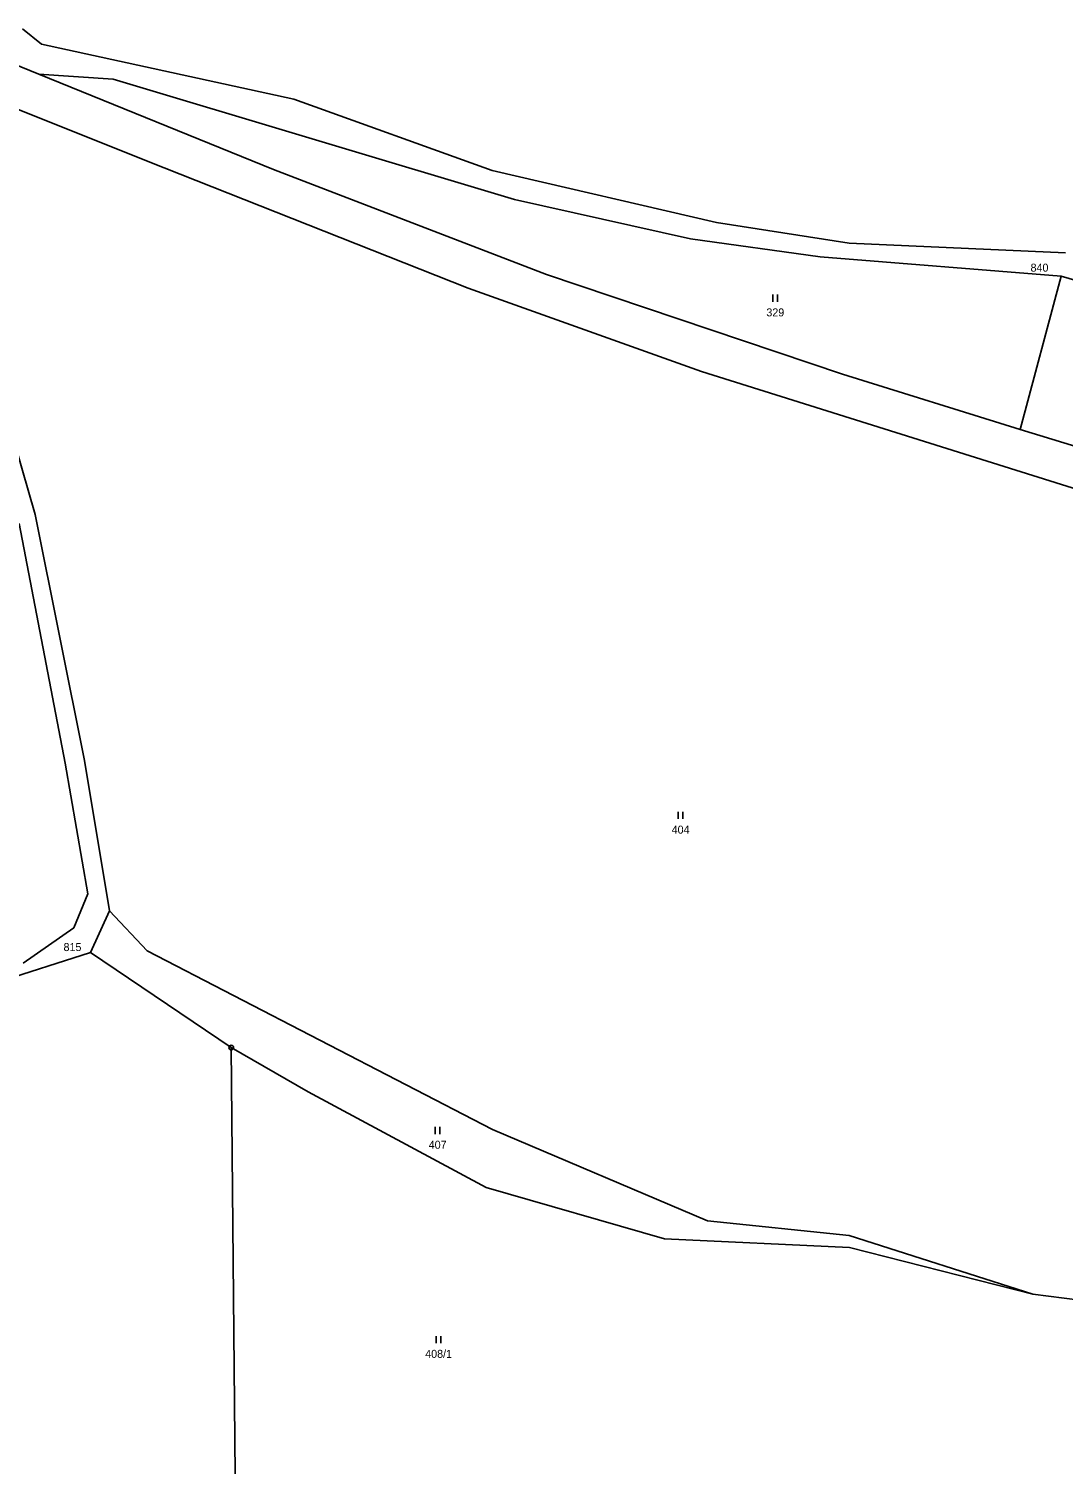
# Model space of a CAD drawing. Extents: x -739410 to -735662, y -942282 to -940043.
# Drawn here: x -736922.9 to -736703.1, y -941395 to -941090 of the extents above; entities that cross this region are included whole.
import ezdxf
from ezdxf.enums import TextEntityAlignment as Align

# ---------------------------------------------------------------- set-up
doc = ezdxf.new("R2010")
doc.units = 0
doc.header["$LTSCALE"] = 0.68
for name, color, linetype, lineweight in [('1', 7, 'Continuous', 25), ('3', 7, 'Continuous', 25), ('8', 7, 'Continuous', 25)]:
    doc.layers.add(name, color=color, linetype=linetype, lineweight=lineweight)
doc.layers.add('2', color=7, linetype='Continuous')

msp = doc.modelspace()

# ---------------------------------------------------------------- linework, layer by layer
at = {"layer": '1'}
for p, q in [((-736920.21, -941093.26), (-736924.25, -941089.98)), ((-736866.59, -941104.95), (-736920.21, -941093.26)), ((-736926.54, -941097.3), (-736920.82, -941099.62)), ((-736904.98, -941100.71), (-736920.82, -941099.62)), ((-736920.82, -941099.62), (-736870.95, -941119.89)), ((-736819.74, -941126.28), (-736904.98, -941100.71)), ((-736894.14, -941119.57), (-736929.52, -941105.46)), ((-736824.48, -941120.14), (-736866.59, -941104.95)), ((-736829.6, -941145.09), (-736894.14, -941119.57)), ((-736870.95, -941119.89), (-736812.92, -941142.23)), ((-736776.85, -941131.18), (-736824.48, -941120.14)), ((-736782.38, -941134.59), (-736819.74, -941126.28)), ((-736748.64, -941135.56), (-736776.85, -941131.18)), ((-736754.82, -941138.43), (-736782.38, -941134.59)), ((-736702.69, -941137.57), (-736748.64, -941135.56)), ((-736703.6, -941142.56), (-736754.82, -941138.43)), ((-736812.92, -941142.23), (-736750.08, -941163.37)), ((-736779.98, -941162.78), (-736829.6, -941145.09)), ((-736712.29, -941175.17), (-736703.6, -941142.56)), ((-736683.12, -941148.47), (-736703.6, -941142.56)), ((-736662.54, -941199.72), (-736779.98, -941162.78)), ((-736750.08, -941163.37), (-736712.29, -941175.17)), ((-736928.69, -941168.35), (-736921.57, -941193.2)), ((-736712.29, -941175.17), (-736665.25, -941189.38)), ((-736921.57, -941193.2), (-736911.1, -941245.45)), ((-736915.21, -941246.01), (-736924.98, -941195.12)), ((-736911.1, -941245.45), (-736905.81, -941277.4)), ((-736910.37, -941273.8), (-736915.21, -941246.01)), ((-736913.36, -941281.04), (-736910.37, -941273.8)), ((-736905.81, -941277.4), (-736909.85, -941286.24)), ((-736905.81, -941277.4), (-736897.75, -941285.92)), ((-736924.12, -941288.53), (-736913.36, -941281.04)), ((-736949.72, -941298.99), (-736909.85, -941286.24)), ((-736909.85, -941286.24), (-736879.91, -941306.45)), ((-736824.39, -941323.89), (-736897.75, -941285.92)), ((-736879.91, -941306.45), (-736879.07, -941397.22)), ((-736879.91, -941306.45), (-736863.55, -941315.84)), ((-736863.55, -941315.84), (-736825.79, -941336.19)), ((-736778.72, -941343.26), (-736824.39, -941323.89)), ((-736825.79, -941336.19), (-736787.88, -941347.08)), ((-736748.66, -941346.42), (-736778.72, -941343.26)), ((-736709.59, -941358.88), (-736748.66, -941346.42)), ((-736748.55, -941348.94), (-736787.88, -941347.08)), ((-736709.59, -941358.88), (-736748.55, -941348.94)), ((-736675.76, -941363.15), (-736709.59, -941358.88))]:
    msp.add_line(p, q, dxfattribs=at)
at = {"layer": '3'}
for p, q in [((-736764.841, -941147.98), (-736764.841, -941146.48)), ((-736763.84, -941147.98), (-736763.84, -941146.48)), ((-736784.961, -941257.88), (-736784.961, -941256.38)), ((-736783.96, -941257.88), (-736783.96, -941256.38)), ((-736836.571, -941324.83), (-736836.571, -941323.33)), ((-736835.57, -941324.83), (-736835.57, -941323.33)), ((-736836.371, -941369.26), (-736836.371, -941367.76)), ((-736835.37, -941369.26), (-736835.37, -941367.76))]:
    msp.add_line(p, q, dxfattribs=at)
at = {"layer": '8'}
for radius in [0.5, 0.0303]:
    msp.add_circle((-736879.91, -941306.4499), radius, dxfattribs=at)

# ---------------------------------------------------------------- texts
at = {"layer": '2'}
for s, p in [('840', (-736708.199, -941141.595)), ('329', (-736764.329, -941151.105)), ('404', (-736784.449, -941261.005)), ('815', (-736913.649, -941285.955)), ('407', (-736836.059, -941327.955)), ('408/1', (-736835.86, -941372.385))]:
    msp.add_text(s, height=1.7, dxfattribs=at).set_placement(p, align=Align.CENTER)

doc.saveas('drawing.dxf')
